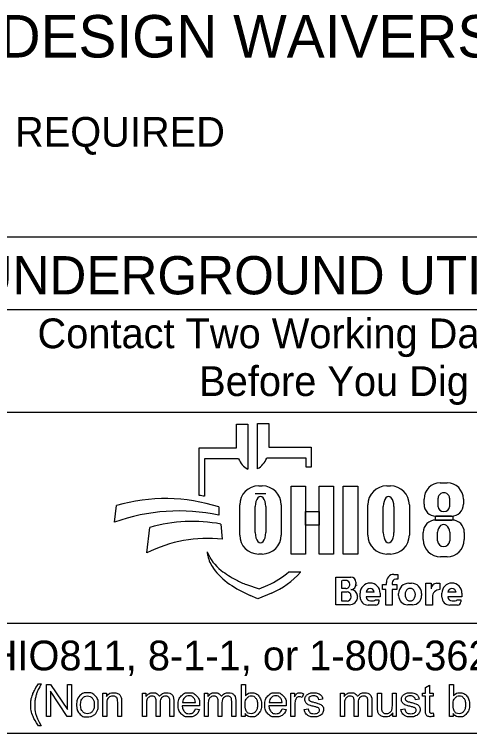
# Model space of a CAD drawing. Extents: x 0 to 34, y 0 to 22.
# Drawn here: x 2.688 to 4.831, y 2.143 to 5.529 of the extents above; entities that cross this region are included whole.
import ezdxf

# ---------------------------------------------------------------- set-up
doc = ezdxf.new("R2010")
doc.units = 0
doc.layers.add('SH_Data', color=7, linetype='Continuous')
doc.layers.add('SH_Text', color=7, linetype='Continuous')

msp = doc.modelspace()

# ---------------------------------------------------------------- linework, layer by layer
at = {"layer": 'SH_Data'}
for p, q in [((6.6275, 4.4803), (2.3775, 4.4803)), ((2.3775, 4.1387), (6.6275, 4.1387)), ((2.3775, 3.6553), (6.6275, 3.6553)), ((6.6275, 2.6607), (2.3775, 2.6607)), ((6.6275, 2.1428), (2.3775, 2.1428))]:
    msp.add_line(p, q, dxfattribs=at)
at = {"layer": 'SH_Text'}
for p, q in [((3.7335, 3.4883), (3.7335, 3.5998)), ((3.7335, 3.5998), (3.7872, 3.5998)), ((3.7872, 3.5998), (3.7872, 3.3877)), ((3.8329, 3.39), (3.8329, 3.6021)), ((3.8329, 3.6021), (3.8865, 3.6021)), ((3.8865, 3.6021), (3.8865, 3.4906)), ((3.5576, 3.2644), (3.5576, 3.4883)), ((3.5576, 3.4883), (3.7335, 3.4883)), ((3.8865, 3.4906), (4.0857, 3.4906)), ((4.0857, 3.4906), (4.0857, 3.3968)), ((3.5828, 3.4369), (3.5828, 3.26)), ((3.7439, 3.4369), (3.5828, 3.4369)), ((4.0625, 3.4392), (3.8761, 3.4392)), ((4.0625, 3.3968), (4.0625, 3.4392)), ((4.0857, 3.3968), (4.0625, 3.3968)), ((4.6931, 3.3231), (4.7258, 3.3231)), ((3.8385, 3.3091), (3.8551, 3.3091)), ((4.4416, 3.3091), (4.4581, 3.3091)), ((3.8718, 3.2721), (3.822, 3.2721)), ((4.683, 3.2111), (4.683, 3.2504)), ((4.7371, 3.2504), (4.7371, 3.2111)), ((3.7491, 3.0776), (3.7491, 3.2196)), ((3.9445, 3.2196), (3.9445, 3.0776)), ((4.3521, 3.0776), (4.3521, 3.2196)), ((4.5476, 3.2196), (4.5476, 3.0776)), ((4.6168, 3.2225), (4.6168, 3.2468)), ((4.8022, 3.2468), (4.8022, 3.2225)), ((3.1602, 3.1381), (3.1696, 3.2162)), ((3.6509, 3.2097), (3.6509, 3.1709)), ((3.822, 3.089), (3.822, 3.2114)), ((3.8718, 3.2114), (3.8718, 3.089)), ((4.425, 3.089), (4.425, 3.2114)), ((4.4748, 3.2114), (4.4748, 3.089)), ((4.7462, 3.1665), (4.6728, 3.1665)), ((3.6608, 3.1291), (3.6671, 3.0582)), ((4.671, 3.1482), (4.7483, 3.1482)), ((3.312, 2.9936), (3.3267, 3.1137)), ((4.6131, 3.0563), (4.6131, 3.0903)), ((4.6806, 3.0503), (4.6806, 3.0912)), ((4.7374, 3.0912), (4.7374, 3.0503)), ((4.8062, 3.0903), (4.8062, 3.0563)), ((3.5997, 2.9807), (3.5967, 2.9986)), ((3.8551, 2.9882), (3.8385, 2.9882)), ((4.4581, 2.9882), (4.4416, 2.9882)), ((4.7252, 2.9753), (4.6941, 2.9753)), ((3.98, 2.9048), (4.0375, 2.9048)), ((4.2013, 2.749), (4.2013, 2.8798)), ((4.2013, 2.8798), (4.2725, 2.8798)), ((4.4739, 2.8926), (4.4934, 2.8926)), ((4.4934, 2.8926), (4.4934, 2.8696)), ((3.7816, 2.8444), (3.841, 2.8239)), ((4.2293, 2.8263), (4.2293, 2.8632)), ((4.2545, 2.8632), (4.2332, 2.8632)), ((4.2963, 2.856), (4.2963, 2.8481)), ((4.4213, 2.8212), (4.4213, 2.8442)), ((4.4213, 2.8442), (4.4406, 2.8442)), ((4.4406, 2.8442), (4.4406, 2.8546)), ((4.4667, 2.8526), (4.4667, 2.8442)), ((4.4667, 2.8442), (4.4883, 2.8442)), ((4.4934, 2.8691), (4.4832, 2.8691)), ((4.4883, 2.8442), (4.4883, 2.8212)), ((4.5451, 2.8508), (4.5573, 2.8508)), ((4.6254, 2.7478), (4.6254, 2.8505)), ((4.6254, 2.8505), (4.6499, 2.8505)), ((4.6499, 2.8505), (4.6499, 2.8237)), ((4.6772, 2.8505), (4.691, 2.8505)), ((4.691, 2.8505), (4.691, 2.8209)), ((3.841, 2.8239), (3.8821, 2.8417)), ((4.2487, 2.8263), (4.2293, 2.8263)), ((4.4362, 2.8212), (4.4213, 2.8212)), ((4.4362, 2.7478), (4.4362, 2.8212)), ((4.4883, 2.8212), (4.4667, 2.8212)), ((4.4667, 2.8212), (4.4667, 2.7478)), ((3.835, 2.7769), (3.7976, 2.7934)), ((3.8983, 2.8044), (3.835, 2.7769)), ((4.2293, 2.7669), (4.2293, 2.8097)), ((4.2293, 2.8097), (4.2548, 2.8097)), ((4.2729, 2.7916), (4.2729, 2.7853)), ((4.3043, 2.7887), (4.3043, 2.7884)), ((4.3159, 2.7858), (4.3159, 2.8042)), ((4.3824, 2.8082), (4.3439, 2.8082)), ((4.4104, 2.7866), (4.344, 2.7866)), ((4.4104, 2.8042), (4.4104, 2.7866)), ((4.4973, 2.7922), (4.4973, 2.8029)), ((4.6051, 2.8029), (4.6051, 2.7922)), ((4.6559, 2.786), (4.6559, 2.7478)), ((4.7008, 2.7858), (4.7008, 2.8042)), ((4.7674, 2.8082), (4.7288, 2.8082)), ((4.7953, 2.7866), (4.7289, 2.7866)), ((4.7953, 2.8042), (4.7953, 2.7866)), ((4.265, 2.749), (4.2013, 2.749)), ((4.2546, 2.7669), (4.2293, 2.7669)), ((4.3892, 2.7478), (4.3538, 2.7478)), ((4.3649, 2.7673), (4.379, 2.7673)), ((4.3876, 2.7729), (4.4045, 2.7729)), ((4.4045, 2.7729), (4.4045, 2.7631)), ((4.4667, 2.7478), (4.4362, 2.7478)), ((4.5623, 2.7494), (4.5401, 2.7494)), ((4.6559, 2.7478), (4.6254, 2.7478)), ((4.7742, 2.7478), (4.7388, 2.7478)), ((4.7498, 2.7673), (4.7639, 2.7673)), ((4.7725, 2.7729), (4.7894, 2.7729)), ((4.7894, 2.7729), (4.7894, 2.7631))]:
    msp.add_line(p, q, dxfattribs=at)
for points in [[(3.991, 3.3081), (4.0589, 3.3081), (4.0589, 2.9881), (3.991, 2.9881)], [(4.1231, 3.3081), (4.1911, 3.3081), (4.1911, 2.9881), (4.1231, 2.9881)], [(4.2364, 3.3081), (4.3052, 3.3081), (4.3052, 2.9881), (4.2364, 2.9881)], [(4.0589, 3.1882), (4.1231, 3.1882), (4.1231, 3.1242), (4.0589, 3.1242)], [(4.6706, 3.1665), (4.7523, 3.1665), (4.7523, 3.1481), (4.6706, 3.1481)]]:
    msp.add_lwpolyline(points, close=True, dxfattribs=at)
for points in [[(2.8021, 2.3766), (2.8153, 2.3766)], [(2.8389, 2.2239), (2.8389, 2.3741), (2.8592, 2.3741), (2.9382, 2.2561), (2.9382, 2.3741), (2.9572, 2.3741), (2.9572, 2.2239), (2.9369, 2.2239), (2.8579, 2.3419), (2.8579, 2.2239), (2.8389, 2.2239)], [(3.7743, 2.2239), (3.7573, 2.2239), (3.7573, 2.3741), (3.7757, 2.3741), (3.7757, 2.3206)], [(4.6233, 2.2558), (4.6233, 2.3185), (4.6097, 2.3185), (4.6097, 2.3328), (4.6233, 2.3328), (4.6233, 2.3597), (4.6417, 2.3708), (4.6417, 2.3328), (4.6601, 2.3328), (4.6601, 2.3185), (4.6417, 2.3185), (4.6417, 2.2547)], [(4.7534, 2.2239), (4.7363, 2.2239), (4.7363, 2.3741), (4.7548, 2.3741), (4.7548, 2.3206)], [(3.1048, 2.2239), (3.1048, 2.3328), (3.1214, 2.3328), (3.1214, 2.3173)], [(3.2912, 2.2239), (3.2912, 2.3328), (3.3077, 2.3328), (3.3077, 2.3174)], [(3.5826, 2.2239), (3.5826, 2.3328), (3.5991, 2.3328), (3.5991, 2.3174)], [(3.9904, 2.2239), (3.9904, 2.3328), (4.007, 2.3328), (4.007, 2.3163)], [(4.0495, 2.3293), (4.043, 2.3122)], [(4.1394, 2.3046), (4.1213, 2.3022)], [(4.2236, 2.2239), (4.2236, 2.3328), (4.2401, 2.3328), (4.2401, 2.3174)], [(4.3979, 2.2654), (4.3979, 2.3328), (4.4164, 2.3328), (4.4164, 2.2724)], [(4.4676, 2.2745), (4.4676, 2.3328), (4.4861, 2.3328), (4.4861, 2.2239), (4.4696, 2.2239)], [(4.594, 2.3046), (4.5759, 2.3022)], [(3.1233, 2.2833), (3.1233, 2.2239), (3.1048, 2.2239)], [(3.1932, 2.2908), (3.1932, 2.2239), (3.1748, 2.2239), (3.1748, 2.2901)], [(3.3097, 2.2803), (3.3097, 2.2239), (3.2912, 2.2239)], [(3.3743, 2.2871), (3.3743, 2.2239), (3.3559, 2.2239), (3.3559, 2.2946)], [(3.4388, 2.2986), (3.4388, 2.2239), (3.4203, 2.2239), (3.4203, 2.2924)], [(3.56, 2.2736), (3.4788, 2.2736)], [(3.4799, 2.2887), (3.5406, 2.2887)], [(3.601, 2.2803), (3.601, 2.2239), (3.5826, 2.2239)], [(3.6657, 2.2871), (3.6657, 2.2239), (3.6473, 2.2239), (3.6473, 2.2946)], [(3.7301, 2.2986), (3.7301, 2.2239), (3.7117, 2.2239), (3.7117, 2.2924)], [(3.968, 2.2736), (3.8868, 2.2736)], [(3.8879, 2.2887), (3.9486, 2.2887)], [(4.0088, 2.2809), (4.0088, 2.2239), (3.9904, 2.2239)], [(4.242, 2.2803), (4.242, 2.2239), (4.2236, 2.2239)], [(4.3067, 2.2871), (4.3067, 2.2239), (4.2883, 2.2239), (4.2883, 2.2946)], [(4.3711, 2.2986), (4.3711, 2.2239), (4.3527, 2.2239), (4.3527, 2.2924)], [(3.5404, 2.2591), (3.5595, 2.2567)], [(3.7743, 2.2375), (3.7743, 2.2239)], [(3.9484, 2.2591), (3.9675, 2.2567)], [(4.053, 2.2564), (4.0712, 2.2593)], [(4.4696, 2.2239), (4.4696, 2.24)], [(4.5076, 2.2564), (4.5258, 2.2593)], [(4.6601, 2.2404), (4.6628, 2.2241)], [(4.7534, 2.2375), (4.7534, 2.2239)], [(2.8153, 2.1798), (2.8021, 2.1798)]]:
    msp.add_lwpolyline(points, dxfattribs=at)
for centre, radius, start, end in [((3.8353, 3.4736), 0.0985, 201.9296, 240.7469), ((3.7847, 3.476), 0.0985, 299.2531, 338.0704), ((4.6931, 3.2468), 0.0763, 90, 180), ((4.7258, 3.2468), 0.0763, 0, 90), ((3.8385, 3.2196), 0.0895, 90, 180), ((3.8551, 3.2196), 0.0895, 0, 90), ((4.4416, 3.2196), 0.0895, 90, 180), ((4.4581, 3.2196), 0.0895, 0, 90), ((3.4295, 2.4554), 0.8191, 79.2074, 81.0007), ((3.3997, 2.4302), 0.8191, 72.1402, 106.3144), ((4.6728, 3.2225), 0.056, 180, 270), ((4.7462, 3.2225), 0.056, 270, 0), ((3.4628, 2.2991), 0.8919, 77.8238, 109.8274), ((3.5267, 2.4094), 0.7322, 79.44, 105.8467), ((4.671, 3.0903), 0.0579, 90, 180), ((4.7483, 3.0903), 0.0579, 0, 90), ((3.5987, 2.4262), 0.6357, 83.8248, 116.8021), ((3.8385, 3.0776), 0.0895, 180, 270), ((3.8551, 3.0776), 0.0895, 270, 0), ((4.4416, 3.0776), 0.0895, 180, 270), ((4.4581, 3.0776), 0.0895, 270, 0), ((4.6941, 3.0563), 0.081, 180, 270), ((4.7252, 3.0563), 0.081, 270, 0), ((3.7841, 3.0707), 0.2008, 201.0457, 232.5314), ((3.741, 3.0048), 0.1433, 189.6817, 216.0884), ((3.8747, 3.1022), 0.3088, 216.0884, 235.7167), ((3.9766, 3.3219), 0.5173, 232.5314, 241.794), ((3.7387, 3.1722), 0.3602, 293.4582, 312.0712), ((3.7387, 3.1722), 0.401, 293.4582, 317.8286), ((4.2725, 2.856), 0.0238, 0, 90), ((4.4739, 2.859), 0.0335, 90, 187.5187), ((4.0412, 3.3465), 0.6044, 235.7167, 246.2325), ((3.8914, 3.1631), 0.3371, 241.794, 250.9821), ((4.2487, 2.845), 0.0187, 270, 2.0582), ((4.2505, 2.8463), 0.0169, 357.8325, 90), ((4.2721, 2.8453), 0.0243, 270, 6.6529), ((4.3631, 2.8042), 0.0473, 0, 180), ((4.4832, 2.8526), 0.0165, 90, 180), ((4.5451, 2.8029), 0.0478, 90, 180), ((4.5573, 2.8029), 0.0478, 0, 90), ((4.6768, 2.8237), 0.0269, 89.2449, 180), ((4.7481, 2.8042), 0.0473, 0, 180), ((4.2722, 2.7889), 0.0321, 4.0748, 90), ((4.2827, 2.8438), 0.0175, 347.4023, 0), ((4.3632, 2.8072), 0.0193, 2.9632, 177.0368), ((4.6908, 2.786), 0.0349, 89.6033, 180), ((4.7481, 2.8072), 0.0193, 2.9632, 177.0368), ((4.2546, 2.7853), 0.0184, 270, 0), ((4.2548, 2.7916), 0.0181, 0, 90), ((4.265, 2.7884), 0.0393, 270, 0), ((4.2714, 2.7887), 0.033, 0, 11.7502), ((4.3538, 2.7858), 0.038, 180, 270), ((4.3649, 2.7883), 0.021, 184.827, 270), ((4.5401, 2.7922), 0.0428, 180, 270), ((4.5623, 2.7922), 0.0428, 270, 0), ((4.7388, 2.7858), 0.038, 180, 270), ((4.7498, 2.7883), 0.021, 184.827, 270), ((4.379, 2.7767), 0.00938, 270, 335.9979), ((4.3892, 2.7631), 0.0152, 270, 0), ((4.7639, 2.7767), 0.00938, 270, 335.9979), ((4.7742, 2.7631), 0.0152, 270, 0)]:
    msp.add_arc(centre, radius, start, end, dxfattribs=at)
for centre, major_axis, ratio, start_param, end_param in [((3.8469, 3.2114), (0, 0.0484), 0.514403, 4.712389, 7.853982), ((4.4499, 3.2114), (0, 0.0484), 0.514403, 4.712389, 7.853982), ((4.71, 3.2504), (0.0271, 0), 0.969373, 0, 3.141593), ((4.71, 3.2111), (0.0271, 0), 0.818453, 3.141593, 6.283185), ((4.709, 3.0912), (0, 0.0358), 0.794529, 4.712389, 7.853982), ((3.8469, 3.089), (0, 0.0484), 0.514403, 1.570796, 4.712389), ((4.4499, 3.089), (0, 0.0484), 0.514403, 1.570796, 4.712389), ((4.709, 3.0503), (0.0284, 0), 0.959837, 3.141593, 6.283185), ((4.5517, 2.7976), (0, 0.029), 0.832186, 4.712389, 7.853982), ((4.5517, 2.7976), (0, 0.0302), 0.797287, 1.570796, 4.712389)]:
    msp.add_ellipse(centre, major_axis=major_axis, ratio=ratio, start_param=start_param, end_param=end_param, dxfattribs=at)
for points in [[(2.8021, 2.1798), (2.7869, 2.199), (2.7763, 2.2248), (2.7657, 2.2506), (2.7657, 2.2783), (2.7657, 2.3026), (2.7736, 2.325), (2.7829, 2.3509), (2.8021, 2.3766)], [(2.8153, 2.3766), (2.8029, 2.3553), (2.7989, 2.3462), (2.7927, 2.332), (2.7891, 2.3167), (2.7847, 2.2975), (2.7847, 2.2782), (2.7847, 2.2289), (2.8153, 2.1798)], [(2.9814, 2.2783), (2.9814, 2.3085), (2.9981, 2.3231), (3.0122, 2.3352), (3.0323, 2.3352), (3.0547, 2.3352), (3.069, 2.3205), (3.0832, 2.3058), (3.0832, 2.2799), (3.0832, 2.2589), (3.0769, 2.2469), (3.0706, 2.2348), (3.0586, 2.2282), (3.0466, 2.2215), (3.0323, 2.2215), (3.0095, 2.2215), (2.9954, 2.2362), (2.9814, 2.2508), (2.9814, 2.2783)], [(3.0003, 2.2783), (3.0003, 2.2574), (3.0094, 2.247), (3.0185, 2.2366), (3.0323, 2.2366), (3.046, 2.2366), (3.0551, 2.2471), (3.0642, 2.2575), (3.0642, 2.279), (3.0642, 2.2991), (3.0551, 2.3095), (3.0459, 2.3199), (3.0323, 2.3199), (3.0185, 2.3199), (3.0094, 2.3096), (3.0003, 2.2992), (3.0003, 2.2783)], [(3.1214, 2.3173), (3.1334, 2.3352), (3.156, 2.3352), (3.1659, 2.3352), (3.1741, 2.3316), (3.1823, 2.3281), (3.1864, 2.3224), (3.1905, 2.3166), (3.1922, 2.3087), (3.1932, 2.3036), (3.1932, 2.2908)], [(3.1748, 2.2901), (3.1748, 2.3013), (3.1726, 2.3069), (3.1705, 2.3125), (3.165, 2.3158), (3.1595, 2.3191), (3.1521, 2.3191), (3.1404, 2.3191), (3.1318, 2.3117), (3.1233, 2.3042), (3.1233, 2.2833)], [(3.3077, 2.3174), (3.3128, 2.3254), (3.3214, 2.3303), (3.3299, 2.3352), (3.3407, 2.3352), (3.3528, 2.3352), (3.3606, 2.3301), (3.3683, 2.3251), (3.3715, 2.3161), (3.3844, 2.3352), (3.4051, 2.3352), (3.4213, 2.3352), (3.43, 2.3262), (3.4388, 2.3172), (3.4388, 2.2986)], [(3.3559, 2.2946), (3.3559, 2.3069), (3.3514, 2.313), (3.3469, 2.3191), (3.3366, 2.3191), (3.3288, 2.3191), (3.3222, 2.315), (3.3156, 2.311), (3.3126, 2.3031), (3.3097, 2.2952), (3.3097, 2.2803)], [(3.4203, 2.2924), (3.4203, 2.3035), (3.4185, 2.3083), (3.4168, 2.3132), (3.412, 2.3162), (3.4073, 2.3191), (3.401, 2.3191), (3.3895, 2.3191), (3.3819, 2.3115), (3.3743, 2.3039), (3.3743, 2.2871)], [(3.5595, 2.2567), (3.555, 2.24), (3.5428, 2.2307), (3.5306, 2.2215), (3.5117, 2.2215), (3.4878, 2.2215), (3.4738, 2.2362), (3.4598, 2.2509), (3.4598, 2.2774), (3.4598, 2.3049), (3.474, 2.32), (3.4881, 2.3352), (3.5106, 2.3352), (3.5324, 2.3352), (3.5463, 2.3203), (3.5601, 2.3055), (3.5601, 2.2785), (3.5601, 2.2769), (3.56, 2.2736)], [(3.5406, 2.2887), (3.5394, 2.3025), (3.5337, 2.3094), (3.5249, 2.3201), (3.5108, 2.3201), (3.4981, 2.3201), (3.4894, 2.3115), (3.4808, 2.303), (3.4799, 2.2887)], [(3.5991, 2.3174), (3.6042, 2.3254), (3.6127, 2.3303), (3.6212, 2.3352), (3.6321, 2.3352), (3.6442, 2.3352), (3.6519, 2.3301), (3.6597, 2.3251), (3.6628, 2.3161), (3.6758, 2.3352), (3.6965, 2.3352), (3.7127, 2.3352), (3.7214, 2.3262), (3.7301, 2.3172), (3.7301, 2.2986)], [(3.6473, 2.2946), (3.6473, 2.3069), (3.6428, 2.313), (3.6383, 2.3191), (3.628, 2.3191), (3.6202, 2.3191), (3.6136, 2.315), (3.607, 2.311), (3.604, 2.3031), (3.601, 2.2952), (3.601, 2.2803)], [(3.7117, 2.2924), (3.7117, 2.3035), (3.7099, 2.3083), (3.7081, 2.3132), (3.7034, 2.3162), (3.6987, 2.3191), (3.6923, 2.3191), (3.6809, 2.3191), (3.6733, 2.3115), (3.6657, 2.3039), (3.6657, 2.2871)], [(3.7741, 2.2792), (3.7741, 2.2596), (3.7794, 2.2509), (3.7881, 2.2366), (3.8029, 2.2366), (3.815, 2.2366), (3.8238, 2.2471), (3.8326, 2.2576), (3.8326, 2.2784), (3.8326, 2.2998), (3.8241, 2.3099), (3.8157, 2.3201), (3.8038, 2.3201), (3.7917, 2.3201), (3.7829, 2.3096), (3.7741, 2.299), (3.7741, 2.2792)], [(3.7757, 2.3206), (3.7874, 2.3352), (3.8055, 2.3352), (3.8155, 2.3352), (3.8245, 2.3311), (3.8335, 2.3271), (3.8392, 2.3198), (3.845, 2.3124), (3.8483, 2.3021), (3.8516, 2.2918), (3.8516, 2.28), (3.8516, 2.252), (3.8378, 2.2368), (3.8239, 2.2215), (3.8046, 2.2215), (3.7853, 2.2215), (3.7743, 2.2375)], [(3.9675, 2.2567), (3.963, 2.24), (3.9508, 2.2307), (3.9386, 2.2215), (3.9196, 2.2215), (3.8958, 2.2215), (3.8818, 2.2362), (3.8678, 2.2509), (3.8678, 2.2774), (3.8678, 2.3049), (3.882, 2.32), (3.8961, 2.3352), (3.9186, 2.3352), (3.9404, 2.3352), (3.9543, 2.3203), (3.9681, 2.3055), (3.9681, 2.2785), (3.9681, 2.2769), (3.968, 2.2736)], [(3.9486, 2.2887), (3.9474, 2.3025), (3.9417, 2.3094), (3.9328, 2.3201), (3.9188, 2.3201), (3.9061, 2.3201), (3.8974, 2.3115), (3.8888, 2.303), (3.8879, 2.2887)], [(4.007, 2.3163), (4.0133, 2.3278), (4.0187, 2.3315), (4.0241, 2.3352), (4.0305, 2.3352), (4.0398, 2.3352), (4.0495, 2.3293)], [(4.043, 2.3122), (4.0363, 2.3162), (4.0295, 2.3162), (4.0235, 2.3162), (4.0187, 2.3125), (4.0139, 2.3089), (4.0119, 2.3024), (4.0088, 2.2926), (4.0088, 2.2809)], [(4.1213, 2.3022), (4.1201, 2.3106), (4.1142, 2.3153), (4.1083, 2.3201), (4.0975, 2.3201), (4.0848, 2.3201), (4.0794, 2.3159), (4.0739, 2.3116), (4.0739, 2.306), (4.0739, 2.3024), (4.0762, 2.2995), (4.0785, 2.2966), (4.0833, 2.2946), (4.086, 2.2936), (4.0996, 2.2899), (4.1192, 2.2847), (4.1269, 2.2813), (4.1347, 2.278), (4.1391, 2.2717), (4.1435, 2.2653), (4.1435, 2.2559), (4.1435, 2.2467), (4.1381, 2.2386), (4.1327, 2.2304), (4.1226, 2.226), (4.1124, 2.2215), (4.0996, 2.2215), (4.0784, 2.2215), (4.0672, 2.2303), (4.0561, 2.2391), (4.053, 2.2564)], [(4.0712, 2.2593), (4.0727, 2.2483), (4.0798, 2.2425), (4.0868, 2.2366), (4.0995, 2.2366), (4.1122, 2.2366), (4.1184, 2.2418), (4.1245, 2.247), (4.1245, 2.254), (4.1245, 2.2602), (4.1191, 2.2638), (4.1153, 2.2663), (4.1002, 2.2701), (4.0799, 2.2752), (4.072, 2.2789), (4.0642, 2.2827), (4.0601, 2.2893), (4.0561, 2.2959), (4.0561, 2.3038), (4.0561, 2.3111), (4.0594, 2.3173), (4.0628, 2.3235), (4.0685, 2.3276), (4.0728, 2.3308), (4.0803, 2.333), (4.0877, 2.3352), (4.0962, 2.3352), (4.109, 2.3352), (4.1187, 2.3315), (4.1284, 2.3278), (4.133, 2.3215), (4.1377, 2.3152), (4.1394, 2.3046)], [(4.2401, 2.3174), (4.2452, 2.3254), (4.2537, 2.3303), (4.2622, 2.3352), (4.2731, 2.3352), (4.2852, 2.3352), (4.2929, 2.3301), (4.3007, 2.3251), (4.3038, 2.3161), (4.3168, 2.3352), (4.3375, 2.3352), (4.3537, 2.3352), (4.3624, 2.3262), (4.3711, 2.3172), (4.3711, 2.2986)], [(4.2883, 2.2946), (4.2883, 2.3069), (4.2838, 2.313), (4.2793, 2.3191), (4.269, 2.3191), (4.2612, 2.3191), (4.2546, 2.315), (4.248, 2.311), (4.245, 2.3031), (4.242, 2.2952), (4.242, 2.2803)], [(4.3527, 2.2924), (4.3527, 2.3035), (4.3509, 2.3083), (4.3491, 2.3132), (4.3444, 2.3162), (4.3397, 2.3191), (4.3333, 2.3191), (4.3219, 2.3191), (4.3143, 2.3115), (4.3067, 2.3039), (4.3067, 2.2871)], [(4.5759, 2.3022), (4.5747, 2.3106), (4.5688, 2.3153), (4.5629, 2.3201), (4.5521, 2.3201), (4.5394, 2.3201), (4.5339, 2.3159), (4.5285, 2.3116), (4.5285, 2.306), (4.5285, 2.3024), (4.5308, 2.2995), (4.533, 2.2966), (4.5378, 2.2946), (4.5406, 2.2936), (4.5542, 2.2899), (4.5737, 2.2847), (4.5815, 2.2813), (4.5893, 2.278), (4.5937, 2.2717), (4.5981, 2.2653), (4.5981, 2.2559), (4.5981, 2.2467), (4.5927, 2.2386), (4.5873, 2.2304), (4.5772, 2.226), (4.567, 2.2215), (4.5542, 2.2215), (4.5329, 2.2215), (4.5218, 2.2303), (4.5107, 2.2391), (4.5076, 2.2564)], [(4.5258, 2.2593), (4.5273, 2.2483), (4.5343, 2.2425), (4.5414, 2.2366), (4.554, 2.2366), (4.5668, 2.2366), (4.5729, 2.2418), (4.5791, 2.247), (4.5791, 2.254), (4.5791, 2.2602), (4.5736, 2.2638), (4.5698, 2.2663), (4.5548, 2.2701), (4.5345, 2.2752), (4.5266, 2.2789), (4.5188, 2.2827), (4.5147, 2.2893), (4.5107, 2.2959), (4.5107, 2.3038), (4.5107, 2.3111), (4.514, 2.3173), (4.5173, 2.3235), (4.5231, 2.3276), (4.5274, 2.3308), (4.5348, 2.333), (4.5423, 2.3352), (4.5508, 2.3352), (4.5636, 2.3352), (4.5733, 2.3315), (4.583, 2.3278), (4.5876, 2.3215), (4.5922, 2.3152), (4.594, 2.3046)], [(4.7532, 2.2792), (4.7532, 2.2596), (4.7585, 2.2509), (4.7672, 2.2366), (4.782, 2.2366), (4.7941, 2.2366), (4.8029, 2.2471), (4.8116, 2.2576), (4.8116, 2.2784), (4.8116, 2.2998), (4.8032, 2.3099), (4.7948, 2.3201), (4.7828, 2.3201), (4.7708, 2.3201), (4.762, 2.3096), (4.7532, 2.299), (4.7532, 2.2792)], [(4.7548, 2.3206), (4.7664, 2.3352), (4.7846, 2.3352), (4.7946, 2.3352), (4.8036, 2.3311), (4.8125, 2.3271), (4.8183, 2.3198), (4.8241, 2.3124), (4.8274, 2.3021), (4.8306, 2.2918), (4.8306, 2.28), (4.8306, 2.252), (4.8168, 2.2368), (4.803, 2.2215), (4.7836, 2.2215), (4.7644, 2.2215), (4.7534, 2.2375)], [(3.4788, 2.2736), (3.4799, 2.2557), (3.489, 2.2462), (3.4981, 2.2366), (3.5117, 2.2366), (3.5219, 2.2366), (3.5291, 2.242), (3.5362, 2.2473), (3.5404, 2.2591)], [(3.8868, 2.2736), (3.8879, 2.2557), (3.897, 2.2462), (3.9061, 2.2366), (3.9197, 2.2366), (3.9299, 2.2366), (3.937, 2.242), (3.9442, 2.2473), (3.9484, 2.2591)], [(4.4164, 2.2724), (4.4164, 2.258), (4.4175, 2.253), (4.4192, 2.2457), (4.4249, 2.2416), (4.4305, 2.2374), (4.4388, 2.2374), (4.4471, 2.2374), (4.4543, 2.2417), (4.4616, 2.2459), (4.4646, 2.2533), (4.4676, 2.2606), (4.4676, 2.2745)], [(4.4696, 2.24), (4.4569, 2.2215), (4.4351, 2.2215), (4.4255, 2.2215), (4.4171, 2.2252), (4.4088, 2.2289), (4.4047, 2.2345), (4.4007, 2.2401), (4.3991, 2.2482), (4.3979, 2.2536), (4.3979, 2.2654)], [(4.6628, 2.2241), (4.655, 2.2224), (4.6488, 2.2224), (4.6388, 2.2224), (4.6333, 2.2256), (4.6278, 2.2288), (4.6255, 2.234), (4.6233, 2.2392), (4.6233, 2.2558)], [(4.6417, 2.2547), (4.6417, 2.2468), (4.6427, 2.2445), (4.6436, 2.2423), (4.6458, 2.2409), (4.648, 2.2396), (4.6521, 2.2396), (4.6551, 2.2396), (4.6601, 2.2404)]]:
    msp.add_open_spline(points, degree=3, dxfattribs=at)

# ---------------------------------------------------------------- texts
for s, height, p in [('ADA DESIGN WAIVERS', 0.2, (1.9944, 5.3256)), ('  NONE REQUIRED                          ', 0.14, (1.9944, 4.9056)), ('UNDERGROUND UTILITIES', 0.18, (2.5057, 4.2106)), ('Contact Two Working Days', 0.14, (2.7972, 3.9571)), ('Before You Dig', 0.14, (3.5583, 3.7321)), ('OHIO811, 8-1-1, or 1-800-362-2764', 0.14, (2.422, 2.4406))]:
    msp.add_text(s, height=height, dxfattribs=at).set_placement(p)

doc.saveas('drawing.dxf')
